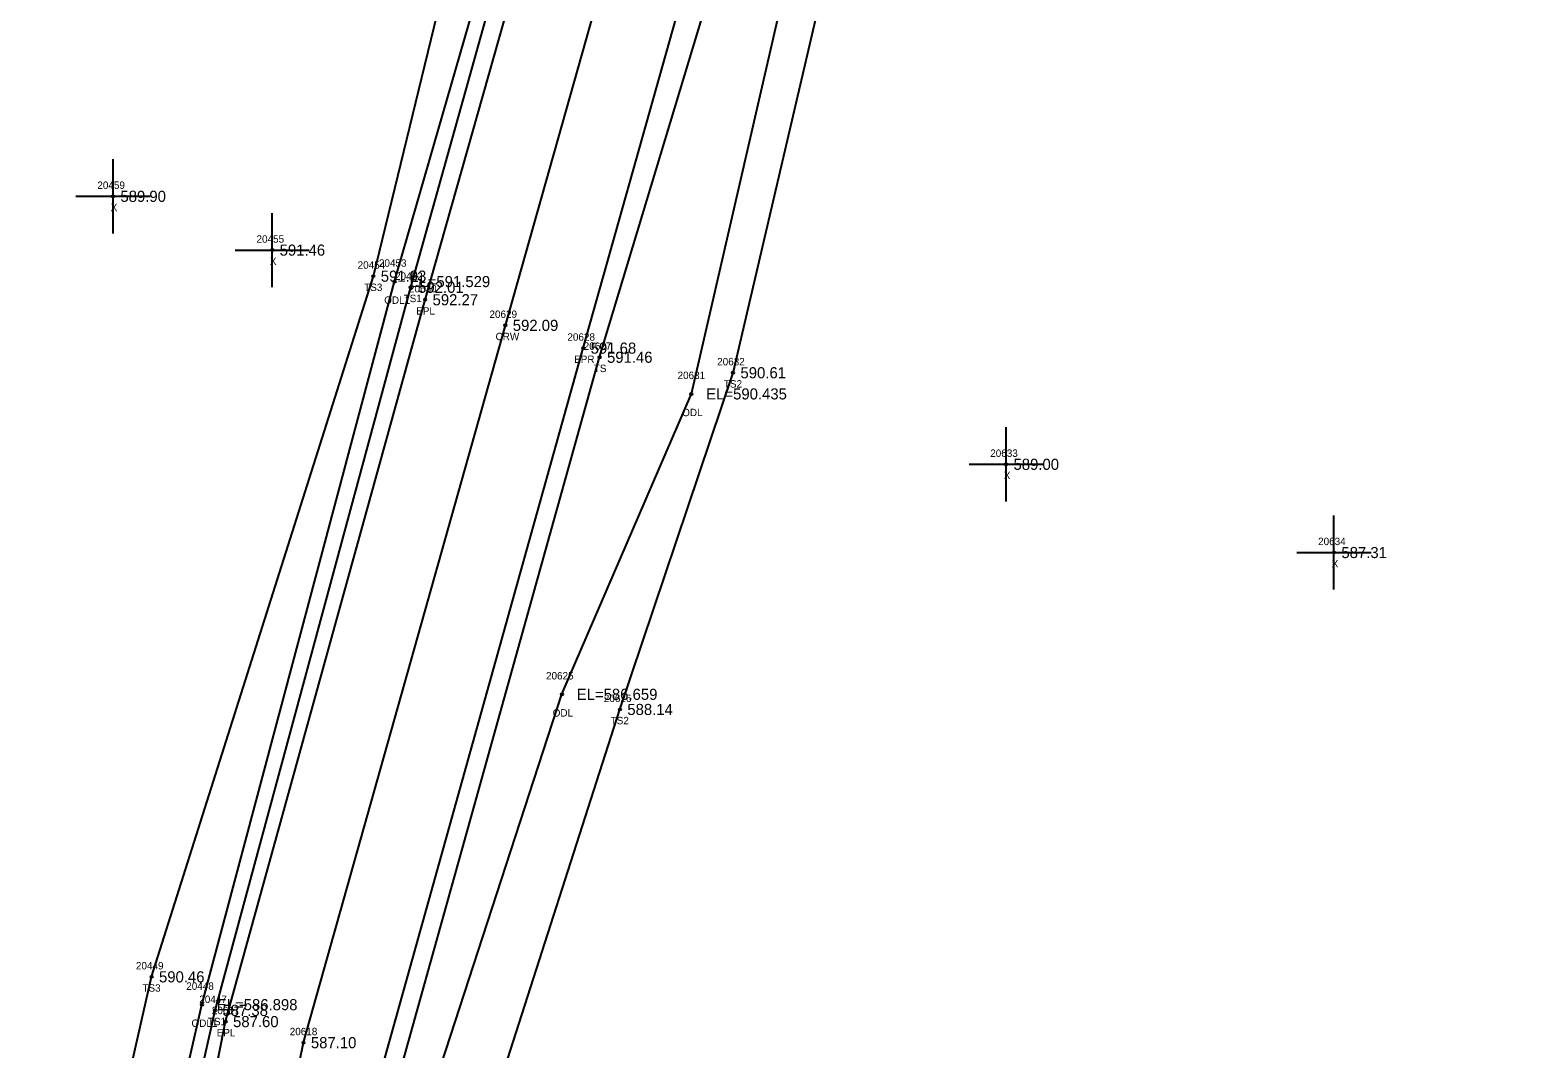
# Model space of a CAD drawing. Extents: x 1695443 to 1696344, y 1087542 to 1090645.
# Drawn here: x 1695695.8 to 1695899, y 1089533.9 to 1089671.2 of the extents above; entities that cross this region are included whole.
import ezdxf

# ---------------------------------------------------------------- set-up
doc = ezdxf.new("R2010")
doc.units = 0
for name, color, linetype in [('RD_DTM_BkLn1', 7, 'Continuous'), ('RD_DTM_BkLn2', 7, 'Continuous'), ('RD_DTM_BkLn_txCode', 7, 'Continuous'), ('RD_EX_H2O', 7, 'Continuous'), ('RD_EX_H2O_txCode', 7, 'Continuous'), ('RD_EX_Misc', 7, 'Continuous'), ('RD_EX_Misc_txCode', 7, 'Continuous'), ('RD_EX_Road', 7, 'Continuous'), ('RD_EX_Road_txCode', 7, 'Continuous'), ('RD_EX_TX_H2O_ELEV', 7, 'Continuous'), ('RD_EX_TX_Misc_ELEV', 7, 'Continuous'), ('RD_EX_TX_Road_ELEV', 7, 'Continuous'), ('RD_HC_Survey_ELEV', 7, 'Continuous'), ('RD_HC_Survey_txCode', 7, 'Continuous'), ('RD_SMD_Locator', 7, 'Continuous')]:
    doc.layers.add(name, color=color, linetype=linetype)

msp = doc.modelspace()

# ---------------------------------------------------------------- linework, layer by layer
at = {"layer": 'RD_DTM_BkLn1'}
msp.add_lwpolyline([(1695813.78, 1089148.1), (1695785.55, 1089189.03), (1695758.89, 1089235.87), (1695740.64, 1089279.02), (1695725.17, 1089334.02), (1695718.27, 1089382.65), (1695717.41, 1089435.13), (1695722.03, 1089482.62), (1695732.64, 1089534.75), (1695759.85, 1089631.43), (1695787.11, 1089727.89), (1695798.89, 1089774.41), (1695810.31, 1089824.5), (1695818.49, 1089870.61), (1695825.85, 1089922.33), (1695831.69, 1089976.57), (1695835.49, 1090019.27), (1695844.06, 1090117.91), (1695852.56, 1090215.73), (1695861.78, 1090313.02), (1695870.8, 1090411.68), (1695879.44, 1090510.15), (1695888.04, 1090606.94)], dxfattribs=at)
at = {"layer": 'RD_DTM_BkLn2'}
for points in [[(1695696.87, 1089328.65), (1695685.13, 1089358.98), (1695692.41, 1089382.13), (1695691.76, 1089435.56), (1695699.73, 1089488.72), (1695712.17, 1089543.62), (1695742.06, 1089638.06), (1695765.36, 1089733.76), (1695777.86, 1089780.36), (1695790.39, 1089828.61), (1695799.49, 1089874.59), (1695809.45, 1089923.14)], [(1695802.49, 1089139.56), (1695797.31, 1089139.87), (1695796.55, 1089145.92), (1695767.85, 1089172.77), (1695752.08, 1089198.99), (1695743.04, 1089224.25), (1695723.93, 1089271.63), (1695706.46, 1089330), (1695701.78, 1089380.95), (1695703.12, 1089435.75), (1695708.88, 1089486.48), (1695720.72, 1089539.1), (1695747.1, 1089636.56), (1695773.41, 1089730.59), (1695786.04, 1089777.66), (1695796.55, 1089826.24), (1695804.53, 1089873.75), (1695809.45, 1089923.14)], [(1695824.1, 1089156.08), (1695822.08, 1089163.12), (1695799.61, 1089199.21), (1695776.92, 1089245.16), (1695754.8, 1089284.38), (1695737.73, 1089336.15), (1695730.34, 1089383.59), (1695730.57, 1089435.13), (1695734.2, 1089480.03), (1695745.77, 1089531.16), (1695772.55, 1089627.13), (1695801.84, 1089724.13), (1695813.32, 1089771.8), (1695823.97, 1089812.55), (1695828.38, 1089814.06), (1695832.18, 1089812.32)], [(1695733.01, 1089422.34), (1695739.17, 1089435.08), (1695740.22, 1089478.28), (1695758.62, 1089527.7), (1695775.29, 1089579.66), (1695790.54, 1089625.04), (1695813.11, 1089721.69), (1695822.77, 1089769.83), (1695832.18, 1089812.32)]]:
    msp.add_lwpolyline(points, dxfattribs=at)
at = {"layer": 'RD_EX_H2O'}
for points in [[(1695696.87, 1089328.65), (1695699.57, 1089380.43), (1695700.06, 1089435.96), (1695707.01, 1089487.43), (1695718.96, 1089539.87), (1695744.93, 1089637.33), (1695772.06, 1089731.31), (1695783.6, 1089778.47), (1695794.38, 1089827.05), (1695802.7, 1089874.04), (1695809.45, 1089923.14)], [(1695733.01, 1089422.34), (1695733.36, 1089435.29), (1695736.08, 1089479.97), (1695750.56, 1089529.82), (1695767.47, 1089581.7), (1695784.92, 1089622.19), (1695808.14, 1089722.97), (1695818.49, 1089770.57), (1695827.73, 1089811.05)]]:
    msp.add_lwpolyline(points, dxfattribs=at)
at = {"layer": 'RD_EX_Misc'}
for p, q in [((1695706.97, 1089643.82), (1695706.97, 1089653.82)), ((1695701.97, 1089648.82), (1695711.97, 1089648.82)), ((1695728.43, 1089636.57), (1695728.43, 1089646.57)), ((1695723.43, 1089641.57), (1695733.43, 1089641.57)), ((1695827.34, 1089607.7), (1695827.34, 1089617.7)), ((1695822.34, 1089612.7), (1695832.34, 1089612.7)), ((1695871.53, 1089595.81), (1695871.53, 1089605.81)), ((1695866.53, 1089600.81), (1695876.53, 1089600.81))]:
    msp.add_line(p, q, dxfattribs=at)
at = {"layer": 'RD_EX_Road'}
for points in [[(1695813.78, 1089148.1), (1695805.56, 1089142.08), (1695776.44, 1089183.94), (1695749.27, 1089231.88), (1695730.49, 1089275.72), (1695714.87, 1089332.12), (1695707.87, 1089381.72), (1695706.58, 1089435.34), (1695711.58, 1089484.26), (1695722.15, 1089537.59), (1695749.04, 1089634.88), (1695776.11, 1089730.43), (1695788.13, 1089777.42), (1695798.89, 1089826.76), (1695807.1, 1089870.03), (1695814.71, 1089923.3), (1695820.51, 1089978.16), (1695824.04, 1090019.79), (1695832.76, 1090119.06), (1695841.25, 1090216.76), (1695850.36, 1090314.41), (1695859.24, 1090411.82), (1695868.09, 1090511.63), (1695876.75, 1090608.38)], [(1695728.69, 1089383.6), (1695727.9, 1089434.83), (1695732.68, 1089480.1), (1695743.4, 1089531.84), (1695770.35, 1089628.36), (1695797.63, 1089725.22), (1695809.49, 1089772.37), (1695818.34, 1089811.57), (1695820.65, 1089823.41), (1695822.99, 1089835.26), (1695829.18, 1089869.37), (1695836.32, 1089920.97), (1695842.44, 1089975.46), (1695846.49, 1090018.55), (1695849.32, 1090055.39), (1695850.91, 1090072.92), (1695855.09, 1090117.49), (1695863.53, 1090214.93), (1695872.56, 1090312.44), (1695881.69, 1090410.78), (1695890.45, 1090509.3), (1695899.01, 1090605.4)]]:
    msp.add_lwpolyline(points, dxfattribs=at)
at = {"layer": 'RD_SMD_Locator'}
for centre in [(1695706.97, 1089648.82), (1695728.43, 1089641.57), (1695742.06, 1089638.06), (1695744.93, 1089637.33), (1695747.1, 1089636.56), (1695749.04, 1089634.88), (1695759.85, 1089631.43), (1695770.35, 1089628.36), (1695772.55, 1089627.13), (1695790.54, 1089625.04), (1695784.92, 1089622.19), (1695827.34, 1089612.7), (1695871.53, 1089600.81), (1695767.47, 1089581.7), (1695775.29, 1089579.66), (1695712.17, 1089543.62), (1695718.96, 1089539.87), (1695720.72, 1089539.1), (1695722.15, 1089537.59), (1695732.64, 1089534.75)]:
    msp.add_circle(centre, 0.15, dxfattribs=at)

# ---------------------------------------------------------------- texts
at = {"layer": 'RD_DTM_BkLn_txCode'}
for s, p in [('20454', (1695739.94, 1089639.06)), ('20452', (1695744.98, 1089637.56)), ('TS3', (1695740.82, 1089636.06)), ('TS1', (1695746.14, 1089634.56)), ('20627', (1695770.41, 1089628.13)), ('TS', (1695771.76, 1089625.13)), ('20632', (1695788.4, 1089626.04)), ('TS2', (1695789.3, 1089623.04)), ('20626', (1695773.12, 1089580.66)), ('TS2', (1695774.04, 1089577.66)), ('20449', (1695710.06, 1089544.62)), ('TS3', (1695710.93, 1089541.62)), ('20447', (1695718.6, 1089540.1)), ('TS1', (1695719.76, 1089537.1))]:
    msp.add_text(s, height=1, dxfattribs=at).set_placement(p)
at = {"layer": 'RD_EX_H2O_txCode'}
for s, p in [('20453', (1695742.81, 1089639.33)), ('ODL1', (1695743.52, 1089634.33)), ('20631', (1695783.06, 1089624.19)), ('ODL', (1695783.68, 1089619.19)), ('20625', (1695765.33, 1089583.7)), ('ODL', (1695766.23, 1089578.7)), ('20448', (1695716.84, 1089541.87)), ('ODL1', (1695717.55, 1089536.87))]:
    msp.add_text(s, height=1, dxfattribs=at).set_placement(p)
at = {"layer": 'RD_EX_Misc_txCode'}
for s, p in [('20459', (1695704.86, 1089649.82)), ('X', (1695706.66, 1089646.82)), ('20455', (1695726.31, 1089642.57)), ('X', (1695728.11, 1089639.57)), ('20633', (1695825.2, 1089613.7)), ('X', (1695827.03, 1089610.7)), ('20634', (1695869.39, 1089601.81)), ('X', (1695871.22, 1089598.81))]:
    msp.add_text(s, height=1, dxfattribs=at).set_placement(p)
at = {"layer": 'RD_EX_Road_txCode'}
for s, p in [('20630', (1695746.86, 1089635.88)), ('EPL', (1695747.83, 1089632.88)), ('20628', (1695768.21, 1089629.36)), ('EPR', (1695769.12, 1089626.36)), ('20617', (1695720.29, 1089538.59)), ('EPL', (1695720.95, 1089535.59))]:
    msp.add_text(s, height=1, dxfattribs=at).set_placement(p)
at = {"layer": 'RD_EX_TX_H2O_ELEV'}
for s, p in [('EL=591.529', (1695746.93, 1089636.58)), ('EL=590.435', (1695786.92, 1089621.44)), ('EL=586.659', (1695769.47, 1089580.95)), ('EL=586.898', (1695720.96, 1089539.12))]:
    msp.add_text(s, height=1.5, dxfattribs=at).set_placement(p)
at = {"layer": 'RD_EX_TX_Misc_ELEV'}
for s, p in [('589.90', (1695707.97, 1089648.07)), ('591.46', (1695729.43, 1089640.82)), ('591.93', (1695743.06, 1089637.31)), ('592.01', (1695748.1, 1089635.81)), ('591.46', (1695773.55, 1089626.38)), ('590.61', (1695791.54, 1089624.29)), ('589.00', (1695828.34, 1089611.95)), ('587.31', (1695872.53, 1089600.06)), ('588.14', (1695776.29, 1089578.91)), ('590.46', (1695713.17, 1089542.87)), ('587.38', (1695721.72, 1089538.35))]:
    msp.add_text(s, height=1.5, dxfattribs=at).set_placement(p)
at = {"layer": 'RD_EX_TX_Road_ELEV'}
for s, p in [('592.27', (1695750.04, 1089634.13)), ('591.68', (1695771.35, 1089627.61)), ('587.60', (1695723.15, 1089536.84))]:
    msp.add_text(s, height=1.5, dxfattribs=at).set_placement(p)
at = {"layer": 'RD_HC_Survey_ELEV'}
for s, p in [('592.09', (1695760.85, 1089630.68)), ('587.10', (1695733.64, 1089534))]:
    msp.add_text(s, height=1.5, dxfattribs=at).set_placement(p)
at = {"layer": 'RD_HC_Survey_txCode'}
for s, p in [('20629', (1695757.71, 1089632.43)), ('CRW', (1695758.53, 1089629.43)), ('20618', (1695730.79, 1089535.75))]:
    msp.add_text(s, height=1, dxfattribs=at).set_placement(p)

doc.saveas('drawing.dxf')
